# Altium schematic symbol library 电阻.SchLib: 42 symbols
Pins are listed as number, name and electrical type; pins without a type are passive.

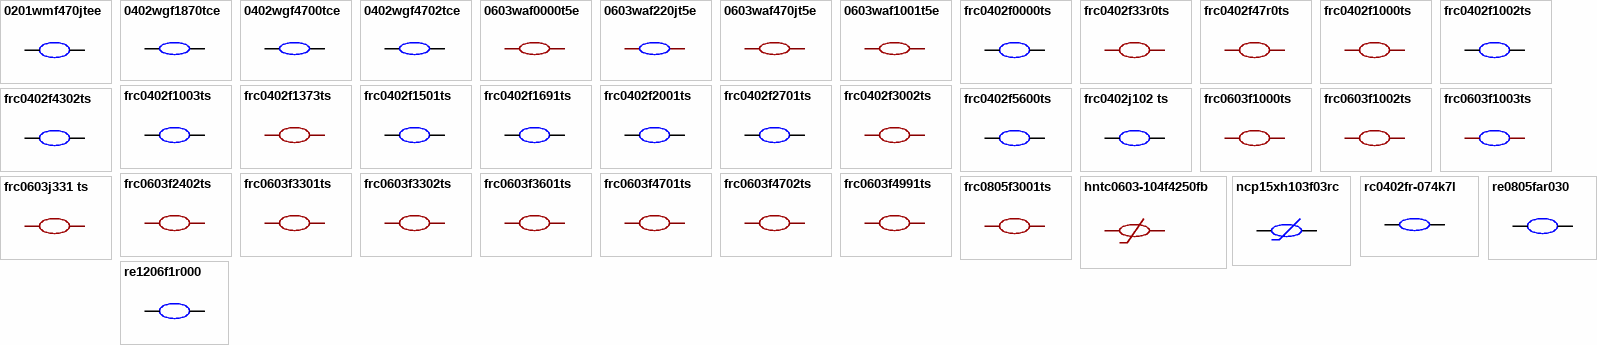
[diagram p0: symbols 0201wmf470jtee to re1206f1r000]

## 0201wmf470jtee
designator R??  (value not drawn)
电阻类型:厚膜电阻;阻值:47Ω;精度:±1%;功率:50mW;最大工作电压:25V;温度系数:±200ppm/℃;; Manufacturer: UNI-ROYAL(厚声); AddInBom: yes; ModelId: 0e006ba4c37b4b73b0e85d5d1c6800cb; ModelName: R0201_L0.6-W0.3-H0.3; ModelTransform: 23.622,11.811,0,0,0,0,0,-0.0005,0; Value: 47Ω; Tolerance: ±1%; Power(Watts): 50mW; Overload Voltage (Max): 25V
footprint R0201
pins: 1, 2

## 0402wgf1870tce
designator R??  (value not drawn)
电阻类型:厚膜电阻;阻值:187Ω;精度:±1%;功率:62.5mW;工作电压:50V;温度系数:±100ppm/℃;; Manufacturer: UNI-ROYAL(厚声); AddInBom: yes; ModelId: 98c88bc2b9094f218f3a3e30a7012738; ModelName: R0402_L1.0-W0.5-H0.4; ModelTransform: 39.37,19.685,0,0,0,0,0,0,0; Value: 187Ω; Tolerance: ±1%; Power(Watts): 62.5mW; Voltage-Supply(Max): 50V
footprint R0402
pins: 1, 2

## 0402wgf4700tce
designator R??  (value not drawn)
电阻类型:厚膜电阻;阻值:470Ω;精度:±1%;功率:62.5mW;工作电压:50V;温度系数:±100ppm/℃;; Manufacturer: UNI-ROYAL(厚声); AddInBom: yes; ModelId: 98c88bc2b9094f218f3a3e30a7012738; ModelName: R0402_L1.0-W0.5-H0.4; ModelTransform: 39.37,19.685,0,0,0,0,0,0,0; Value: 470Ω; Tolerance: ±1%; Power(Watts): 62.5mW; Voltage-Supply(Max): 50V
footprint R0402
pins: 1, 2

## 0402wgf4702tce
designator R??  (value not drawn)
电阻类型:厚膜电阻;阻值:47kΩ;精度:±1%;功率:62.5mW;工作电压:50V;温度系数:±100ppm/℃;; Manufacturer: UNI-ROYAL(厚声); AddInBom: yes; ModelId: 98c88bc2b9094f218f3a3e30a7012738; ModelName: R0402_L1.0-W0.5-H0.4; ModelTransform: 39.37,19.685,0,0,0,0,0,0,0; Value: 47kΩ; Tolerance: ±1%; Power(Watts): 62.5mW; Voltage-Supply(Max): 50V
footprint R0402
pins: 1, 2

## 0603waf0000t5e
designator R??  (value not drawn)
电阻类型:厚膜电阻;阻值:0Ω;精度:±1%;功率:100mW;工作电压:75V;温度系数:-;; Manufacturer: UNI-ROYAL(厚声); AddInBom: yes; ModelId: fc143cca1e79419f9cd78b61e9279f08; ModelName: R0603; ModelTransform: 31.8897,63.7794,0,90,0,0,0,0,0; Value: 0Ω; Tolerance: ±1%; Power(Watts): 100mW; Voltage-Supply(Max): 75V
footprint R0603
pins: 1, 2

## 0603waf220jt5e
designator R??  (value not drawn)
电阻类型:厚膜电阻;阻值:22Ω;精度:±1%;功率:100mW;最大工作电压:75V;温度系数:±100ppm/℃;; Manufacturer: UNI-ROYAL(厚声); AddInBom: yes; ModelId: fc143cca1e79419f9cd78b61e9279f08; ModelName: R0603; ModelTransform: 31.8897,63.7794,0,90,0,0,0,0,0; Value: 22Ω; Tolerance: ±1%; Power(Watts): 100mW; Overload Voltage (Max): 75V
footprint R0603
pins: 1, 2

## 0603waf470jt5e
designator R??  (value not drawn)
电阻类型:厚膜电阻;阻值:47Ω;精度:±1%;功率:100mW;工作电压:75V;温度系数:±100ppm/℃;; Manufacturer: UNI-ROYAL(厚声); AddInBom: yes; ModelId: fc143cca1e79419f9cd78b61e9279f08; ModelName: R0603; ModelTransform: 31.8897,63.7794,0,90,0,0,0,0,0; Value: 47Ω; Tolerance: ±1%; Power(Watts): 100mW; Voltage-Supply(Max): 75V
footprint R0603
pins: 1, 2

## 0603waf1001t5e
designator R??  (value not drawn)
电阻类型:厚膜电阻;阻值:1kΩ;精度:±1%;功率:100mW;工作电压:75V;温度系数:±100ppm/℃;; Manufacturer: UNI-ROYAL(厚声); AddInBom: yes; ModelId: fc143cca1e79419f9cd78b61e9279f08; ModelName: R0603; ModelTransform: 31.8897,63.7794,0,90,0,0,0,0,0; Value: 1kΩ; Tolerance: ±1%; Power(Watts): 100mW; Voltage-Supply(Max): 75V
footprint R0603
pins: 1, 2

## frc0402f0000ts
designator R??  (value not drawn)
电阻类型:厚膜电阻;阻值:0Ω;精度:±1%;功率:62.5mW;工作电压:50V;温度系数:±400ppm/℃;; Manufacturer: FOJAN(富捷); AddInBom: yes; ModelId: 98c88bc2b9094f218f3a3e30a7012738; ModelName: R0402_L1.0-W0.5-H0.4; ModelTransform: 39.37,19.685,0,0,0,0,0,0,0; Value: 0Ω; Tolerance: ±1%; Power(Watts): 62.5mW; Voltage-Supply(Max): 50V
footprint R0402
pins: 1, 2

## frc0402f33r0ts
designator R??  (value not drawn)
电阻类型:厚膜电阻;阻值:33Ω;精度:±1%;功率:62.5mW;工作电压:50V;温度系数:±100ppm/℃;; Manufacturer: FOJAN(富捷); AddInBom: yes; ModelId: 98c88bc2b9094f218f3a3e30a7012738; ModelName: R0402_L1.0-W0.5-H0.4; ModelTransform: 39.37,19.685,0,0,0,0,0,0,0; Value: 33Ω; Tolerance: ±1%; Power(Watts): 62.5mW; Voltage-Supply(Max): 50V
footprint R0402
pins: 1, 2

## frc0402f47r0ts
designator R??  (value not drawn)
电阻类型:厚膜电阻;阻值:47Ω;精度:±1%;功率:62.5mW;工作电压:50V;温度系数:±100ppm/℃;; Manufacturer: FOJAN(富捷); AddInBom: yes; ModelId: 98c88bc2b9094f218f3a3e30a7012738; ModelName: R0402_L1.0-W0.5-H0.4; ModelTransform: 39.37,19.685,0,0,0,0,0,0,0; Value: 47Ω; Tolerance: ±1%; Power(Watts): 62.5mW; Voltage-Supply(Max): 50V
footprint R0402
pins: 1, 2

## frc0402f1000ts
designator R??  (value not drawn)
电阻类型:厚膜电阻;阻值:100Ω;精度:±1%;功率:62.5mW;工作电压:50V;温度系数:±100ppm/℃;; Manufacturer: FOJAN(富捷); AddInBom: yes; ModelId: 98c88bc2b9094f218f3a3e30a7012738; ModelName: R0402_L1.0-W0.5-H0.4; ModelTransform: 39.37,19.685,0,0,0,0,0,0,0; Value: 100Ω; Tolerance: ±1%; Power(Watts): 62.5mW; Voltage-Supply(Max): 50V
footprint R0402
pins: 1, 2

## frc0402f1002ts
designator R??  (value not drawn)
电阻类型:厚膜电阻;阻值:10kΩ;精度:±1%;功率:62.5mW;工作电压:50V;温度系数:±100ppm/℃;; Manufacturer: FOJAN(富捷); AddInBom: yes; ModelId: 98c88bc2b9094f218f3a3e30a7012738; ModelName: R0402_L1.0-W0.5-H0.4; ModelTransform: 39.37,19.685,0,0,0,0,0,0,0; Value: 10kΩ; Tolerance: ±1%; Power(Watts): 62.5mW; Voltage-Supply(Max): 50V
footprint R0402
pins: 1, 2

## frc0402f1003ts
designator R??  (value not drawn)
电阻类型:厚膜电阻;阻值:100kΩ;精度:±1%;功率:62.5mW;工作电压:50V;温度系数:±100ppm/℃;; Manufacturer: FOJAN(富捷); AddInBom: yes; ModelId: 98c88bc2b9094f218f3a3e30a7012738; ModelName: R0402_L1.0-W0.5-H0.4; ModelTransform: 39.37,19.685,0,0,0,0,0,0,0; Value: 100kΩ; Tolerance: ±1%; Power(Watts): 62.5mW; Voltage-Supply(Max): 50V
footprint R0402
pins: 1, 2

## frc0402f1373ts
designator R??  (value not drawn)
电阻类型:厚膜电阻;阻值:137kΩ;精度:±1%;功率:62.5mW;工作电压:50V;温度系数:±100ppm/℃;; Manufacturer: FOJAN(富捷); AddInBom: yes; ModelId: 98c88bc2b9094f218f3a3e30a7012738; ModelName: R0402_L1.0-W0.5-H0.4; ModelTransform: 39.37,19.685,0,0,0,0,0,0,0; Value: 137kΩ; Tolerance: ±1%; Power(Watts): 62.5mW; Voltage-Supply(Max): 50V
footprint R0402
pins: 1, 2

## frc0402f1501ts
designator R??  (value not drawn)
电阻类型:厚膜电阻;阻值:1.5kΩ;精度:±1%;功率:62.5mW;工作电压:50V;温度系数:±100ppm/℃;; Manufacturer: FOJAN(富捷); AddInBom: yes; ModelId: 98c88bc2b9094f218f3a3e30a7012738; ModelName: R0402_L1.0-W0.5-H0.4; ModelTransform: 39.37,19.685,0,0,0,0,0,0,0; Value: 1.5kΩ; Tolerance: ±1%; Power(Watts): 62.5mW; Voltage-Supply(Max): 50V
footprint R0402
pins: 1, 2

## frc0402f1691ts
designator R??  (value not drawn)
电阻类型:厚膜电阻;阻值:1.69kΩ;精度:±1%;功率:62.5mW;工作电压:50V;温度系数:±100ppm/℃;; Manufacturer: FOJAN(富捷); AddInBom: yes; ModelId: 98c88bc2b9094f218f3a3e30a7012738; ModelName: R0402_L1.0-W0.5-H0.4; ModelTransform: 39.37,19.685,0,0,0,0,0,0,0; Value: 1.69kΩ; Tolerance: ±1%; Power(Watts): 62.5mW; Voltage-Supply(Max): 50V
footprint R0402
pins: 1, 2

## frc0402f2001ts
designator R??  (value not drawn)
电阻类型:厚膜电阻;阻值:2kΩ;精度:±1%;功率:62.5mW;工作电压:50V;温度系数:±100ppm/℃;; Manufacturer: FOJAN(富捷); AddInBom: yes; ModelId: 98c88bc2b9094f218f3a3e30a7012738; ModelName: R0402_L1.0-W0.5-H0.4; ModelTransform: 39.37,19.685,0,0,0,0,0,0,0; Value: 2kΩ; Tolerance: ±1%; Power(Watts): 62.5mW; Voltage-Supply(Max): 50V
footprint R0402
pins: 1, 2

## frc0402f2701ts
designator R??  (value not drawn)
电阻类型:厚膜电阻;阻值:2.7kΩ;精度:±1%;功率:62.5mW;工作电压:50V;温度系数:±100ppm/℃;; Manufacturer: FOJAN(富捷); AddInBom: yes; ModelId: 98c88bc2b9094f218f3a3e30a7012738; ModelName: R0402_L1.0-W0.5-H0.4; ModelTransform: 39.37,19.685,0,0,0,0,0,0,0; Value: 2.7kΩ; Tolerance: ±1%; Power(Watts): 62.5mW; Voltage-Supply(Max): 50V
footprint R0402
pins: 1, 2

## frc0402f3002ts
designator R??  (value not drawn)
电阻类型:厚膜电阻;阻值:30kΩ;精度:±1%;功率:62.5mW;工作电压:50V;温度系数:±100ppm/℃;; Manufacturer: FOJAN(富捷); AddInBom: yes; ModelId: 98c88bc2b9094f218f3a3e30a7012738; ModelName: R0402_L1.0-W0.5-H0.4; ModelTransform: 39.37,19.685,0,0,0,0,0,0,0; Value: 30kΩ; Tolerance: ±1%; Power(Watts): 62.5mW; Voltage-Supply(Max): 50V
footprint R0402
pins: 1, 2

## frc0402f4302ts
designator R??  (value not drawn)
电阻类型:厚膜电阻;阻值:43kΩ;精度:±1%;功率:62.5mW;工作电压:50V;温度系数:±100ppm/℃;; Manufacturer: FOJAN(富捷); AddInBom: yes; ModelId: 98c88bc2b9094f218f3a3e30a7012738; ModelName: R0402_L1.0-W0.5-H0.4; ModelTransform: 39.37,19.685,0,0,0,0,0,0,0; Value: 43kΩ; Tolerance: ±1%; Power(Watts): 62.5mW; Voltage-Supply(Max): 50V
footprint R0402
pins: 1, 2

## frc0402f5600ts
designator R??  (value not drawn)
电阻类型:厚膜电阻;阻值:560Ω;精度:±1%;功率:62.5mW;工作电压:50V;温度系数:±100ppm/℃;; Manufacturer: FOJAN(富捷); AddInBom: yes; ModelId: 98c88bc2b9094f218f3a3e30a7012738; ModelName: R0402_L1.0-W0.5-H0.4; ModelTransform: 39.37,19.685,0,0,0,0,0,0,0; Value: 560Ω; Tolerance: ±1%; Power(Watts): 62.5mW; Voltage-Supply(Max): 50V
footprint R0402
pins: 1, 2

## frc0402j102 ts
designator R??  (value not drawn)
电阻类型:厚膜电阻;阻值:1kΩ;精度:±5%;功率:62.5mW;工作电压:50V;温度系数:±100ppm/℃;; Manufacturer: FOJAN(富捷); AddInBom: yes; ModelId: 98c88bc2b9094f218f3a3e30a7012738; ModelName: R0402_L1.0-W0.5-H0.4; ModelTransform: 39.37,19.685,0,0,0,0,0,0,0; Value: 1kΩ; Tolerance: ±5%; Power(Watts): 62.5mW; Voltage-Supply(Max): 50V
footprint R0402
pins: 1, 2

## frc0603f1000ts
designator R??  (value not drawn)
电阻类型:厚膜电阻;阻值:100Ω;精度:±1%;功率:100mW;工作电压:75V;温度系数:±100ppm/℃;; Manufacturer: FOJAN(富捷); AddInBom: yes; ModelId: fc143cca1e79419f9cd78b61e9279f08; ModelName: R0603; ModelTransform: 31.8897,63.7794,0,90,0,0,0,0,0; Value: 100Ω; Tolerance: ±1%; Power(Watts): 100mW; Voltage-Supply(Max): 75V
footprint R0603
pins: 1, 2

## frc0603f1002ts
designator R??  (value not drawn)
电阻类型:厚膜电阻;阻值:10kΩ;精度:±1%;功率:100mW;工作电压:75V;温度系数:±100ppm/℃;; Manufacturer: FOJAN(富捷); AddInBom: yes; ModelId: fc143cca1e79419f9cd78b61e9279f08; ModelName: R0603; ModelTransform: 31.8897,63.7794,0,90,0,0,0,0,0; Value: 10kΩ; Tolerance: ±1%; Power(Watts): 100mW; Voltage-Supply(Max): 75V
footprint R0603
pins: 1, 2

## frc0603f1003ts
designator R??  (value not drawn)
电阻类型:厚膜电阻;阻值:100kΩ;精度:±1%;功率:100mW;工作电压:75V;温度系数:±100ppm/℃;; Manufacturer: FOJAN(富捷); AddInBom: yes; ModelId: fc143cca1e79419f9cd78b61e9279f08; ModelName: R0603; ModelTransform: 31.8897,63.7794,0,90,0,0,0,0,0; Value: 100kΩ; Tolerance: ±1%; Power(Watts): 100mW; Voltage-Supply(Max): 75V
footprint R0603
pins: 1, 2

## frc0603f2402ts
designator R??  (value not drawn)
电阻类型:厚膜电阻;阻值:24kΩ;精度:±1%;功率:100mW;工作电压:75V;温度系数:±100ppm/℃;; Manufacturer: FOJAN(富捷); AddInBom: yes; ModelId: fc143cca1e79419f9cd78b61e9279f08; ModelName: R0603; ModelTransform: 31.8897,63.7794,0,90,0,0,0,0,0; Value: 24kΩ; Tolerance: ±1%; Power(Watts): 100mW; Voltage-Supply(Max): 75V
footprint R0603
pins: 1, 2

## frc0603f3301ts
designator R??  (value not drawn)
电阻类型:厚膜电阻;阻值:3.3kΩ;精度:±1%;功率:100mW;工作电压:75V;温度系数:±100ppm/℃;; Manufacturer: FOJAN(富捷); AddInBom: yes; ModelId: fc143cca1e79419f9cd78b61e9279f08; ModelName: R0603; ModelTransform: 31.8897,63.7794,0,90,0,0,0,0,0; Value: 3.3kΩ; Tolerance: ±1%; Power(Watts): 100mW; Voltage-Supply(Max): 75V
footprint R0603
pins: 1, 2

## frc0603f3302ts
designator R??  (value not drawn)
电阻类型:厚膜电阻;阻值:33kΩ;精度:±1%;功率:100mW;工作电压:75V;温度系数:±100ppm/℃;; Manufacturer: FOJAN(富捷); AddInBom: yes; ModelId: fc143cca1e79419f9cd78b61e9279f08; ModelName: R0603; ModelTransform: 31.8897,63.7794,0,90,0,0,0,0,0; Value: 33kΩ; Tolerance: ±1%; Power(Watts): 100mW; Voltage-Supply(Max): 75V
footprint R0603
pins: 1, 2

## frc0603f3601ts
designator R??  (value not drawn)
电阻类型:厚膜电阻;阻值:3.6kΩ;精度:±1%;功率:100mW;工作电压:75V;温度系数:±100ppm/℃;; Manufacturer: FOJAN(富捷); AddInBom: yes; ModelId: fc143cca1e79419f9cd78b61e9279f08; ModelName: R0603; ModelTransform: 31.8897,63.7794,0,90,0,0,0,0,0; Value: 3.6kΩ; Tolerance: ±1%; Power(Watts): 100mW; Voltage-Supply(Max): 75V
footprint R0603
pins: 1, 2

## frc0603f4701ts
designator R??  (value not drawn)
电阻类型:厚膜电阻;阻值:4.7kΩ;精度:±1%;功率:100mW;工作电压:75V;温度系数:±100ppm/℃;; Manufacturer: FOJAN(富捷); AddInBom: yes; ModelId: fc143cca1e79419f9cd78b61e9279f08; ModelName: R0603; ModelTransform: 31.8897,63.7794,0,90,0,0,0,0,0; Value: 4.7kΩ; Tolerance: ±1%; Power(Watts): 100mW; Voltage-Supply(Max): 75V
footprint R0603
pins: 1, 2

## frc0603f4702ts
designator R??  (value not drawn)
电阻类型:厚膜电阻;阻值:47kΩ;精度:±1%;功率:100mW;工作电压:75V;温度系数:±100ppm/℃;; Manufacturer: FOJAN(富捷); AddInBom: yes; ModelId: fc143cca1e79419f9cd78b61e9279f08; ModelName: R0603; ModelTransform: 31.8897,63.7794,0,90,0,0,0,0,0; Value: 47kΩ; Tolerance: ±1%; Power(Watts): 100mW; Voltage-Supply(Max): 75V
footprint R0603
pins: 1, 2

## frc0603f4991ts
designator R??  (value not drawn)
电阻类型:厚膜电阻;阻值:4.99kΩ;精度:±1%;功率:100mW;工作电压:75V;温度系数:±100ppm/℃;; Manufacturer: FOJAN(富捷); AddInBom: yes; ModelId: fc143cca1e79419f9cd78b61e9279f08; ModelName: R0603; ModelTransform: 31.8897,63.7794,0,90,0,0,0,0,0; Value: 4.99kΩ; Tolerance: ±1%; Power(Watts): 100mW; Voltage-Supply(Max): 75V
footprint R0603
pins: 1, 2

## frc0603j331 ts
designator R??  (value not drawn)
电阻类型:厚膜电阻;阻值:330Ω;精度:±5%;功率:100mW;工作电压:75V;温度系数:±100ppm/℃;; Manufacturer: FOJAN(富捷); AddInBom: yes; ModelId: fc143cca1e79419f9cd78b61e9279f08; ModelName: R0603; ModelTransform: 31.8897,63.7794,0,90,0,0,0,0,0; Value: 330Ω; Tolerance: ±5%; Power(Watts): 100mW; Voltage-Supply(Max): 75V
footprint R0603
pins: 1, 2

## frc0805f3001ts
designator R??  (value not drawn)
电阻类型:厚膜电阻;阻值:3kΩ;精度:±1%;功率:125mW;工作电压:150V;温度系数:±100ppm/℃;; Manufacturer: FOJAN(富捷); AddInBom: yes; ModelId: 37a81e68749a4138bd2dfa6897b24b85; ModelName: R0805_L2.0-W1.3-H0.6; ModelTransform: 78.74,51.181,0,0,0,0,0,-0.0005,0; Value: 3kΩ; Tolerance: ±1%; Power(Watts): 125mW; Voltage-Supply(Max): 150V
footprint R0805
pins: 1, 2

## hntc0603-104f4250fb
designator R??  (value not drawn)
功率:100mW;阻值:100kΩ;电阻精度:±1%;B值精度:±1%;B值(25℃/50℃):4250K;最大稳态电流(25℃):10uA;; Manufacturer: R+O(宏嘉诚); AddInBom: yes; ModelId: fc143cca1e79419f9cd78b61e9279f08; ModelName: R0603; ModelTransform: 31.8897,63.7794,0,90,0,0,0,0,0; Power(Watts): 100mW; Resistance @ 25℃: 100kΩ; Resistance Tolerance: ±1%; B Constant (25℃/50℃): 4250K; Steady State Current (Max): 10uA; Dissipation Factor: 1mW/℃; Thermal Time Constant: 5s; Pitch: 0.3mm
footprint R0603
pins: 1, 2

## ncp15xh103f03rc
designator R??  (value not drawn)
阻值:10kΩ;B值(25℃/50℃):3380K;电阻精度:±1%;功率:100mW;B值精度:±1%;最大稳态电流(25℃):310uA;; Manufacturer: muRata(村田); AddInBom: yes; ModelId: 98c88bc2b9094f218f3a3e30a7012738; ModelName: R0402_L1.0-W0.5-H0.4; ModelTransform: 39.37,19.685,0,0,0,0,0,0,0; Resistance @ 25℃: 10kΩ; B Constant (25℃/50℃): 3380K; Resistance Tolerance: ±1%; B Constant (25℃/85℃): 3434K; B Constant (25℃/100℃): 3455K; Power(Watts): 100mW; Steady State Current (Max): 310uA; Dissipation Factor: 1mW/℃
footprint R0402
pins: 1, 2

## rc0402fr-074k7l
designator R??  (value not drawn)
电阻类型:厚膜电阻;阻值:4.7kΩ;精度:±1%;功率:62.5mW;工作电压:50V;温度系数:±100ppm/℃;; Manufacturer: YAGEO(国巨); AddInBom: yes; ModelId: 98c88bc2b9094f218f3a3e30a7012738; ModelName: R0402_L1.0-W0.5-H0.4; ModelTransform: 39.37,19.685,0,0,0,0,0,0,0; Value: 4.7kΩ; Tolerance: ±1%; Power(Watts): 62.5mW; Voltage-Supply(Max): 50V
footprint R0402
pins: 1, 2

## re0805far030
designator R??  (value not drawn)
电阻类型:合金电阻;阻值:30mΩ;精度:±1%;功率:500mW;温度系数:±50ppm/℃;安装方式:贴片;; Manufacturer: JIERR(捷而瑞); AddInBom: yes; ModelId: 37a81e68749a4138bd2dfa6897b24b85; ModelName: R0805_L2.0-W1.3-H0.6; ModelTransform: 78.74,51.181,0,0,0,0,0,-0.0005,0; Value: 30mΩ; Tolerance: ±1%; Power(Watts): 500mW
footprint R0805
pins: 1, 2

## re1206f1r000
designator R??  (value not drawn)
电阻类型:采样电阻；合金电阻;阻值:0Ω;精度:±1%;功率:1W;安装方式:贴片;; Manufacturer: JIERR(捷而瑞); AddInBom: yes; ModelId: 89a1f13db2384da588040e0b3c55bf66; ModelName: R1206_L3.2-W1.6-H0.6; ModelTransform: 125.984,62.992,0,0,0,0,0,0,0; Value: 0Ω; Tolerance: ±1%; Power(Watts): 1W
footprint R1206
pins: 1, 2

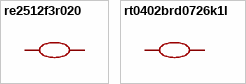
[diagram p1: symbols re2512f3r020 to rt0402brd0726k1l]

## re2512f3r020
designator R??  (value not drawn)
电阻类型:采样电阻；合金电阻;阻值:20mΩ;精度:±1%;功率:3W;温度系数:±50ppm/℃;安装方式:贴片;; Manufacturer: JIERR(捷而瑞); AddInBom: yes; ModelId: 3c946b39f1b547de9af067cb1ede82cc; ModelName: RES-SMD_L6.4-W3.2-R2512; ModelTransform: 252.7554,126.7714,0,0,0,0,0,0,0; Value: 20mΩ; Tolerance: ±1%; Power(Watts): 3W
footprint RES-SMD_L6.4-W3.2-R2512
pins: 1, 2

## rt0402brd0726k1l
designator R??  (value not drawn)
电阻类型:薄膜电阻;阻值:26.1kΩ;精度:±0.1%;功率:62.5mW;工作电压:50V;温度系数:±25ppm/℃;; Manufacturer: YAGEO(国巨); AddInBom: yes; ModelId: 98c88bc2b9094f218f3a3e30a7012738; ModelName: R0402_L1.0-W0.5-H0.4; ModelTransform: 39.37,19.685,0,0,0,0,0,0,0; Value: 26.1kΩ; Tolerance: ±0.1%; Power(Watts): 62.5mW; Voltage-Supply(Max): 50V
footprint R0402
pins: 1, 2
